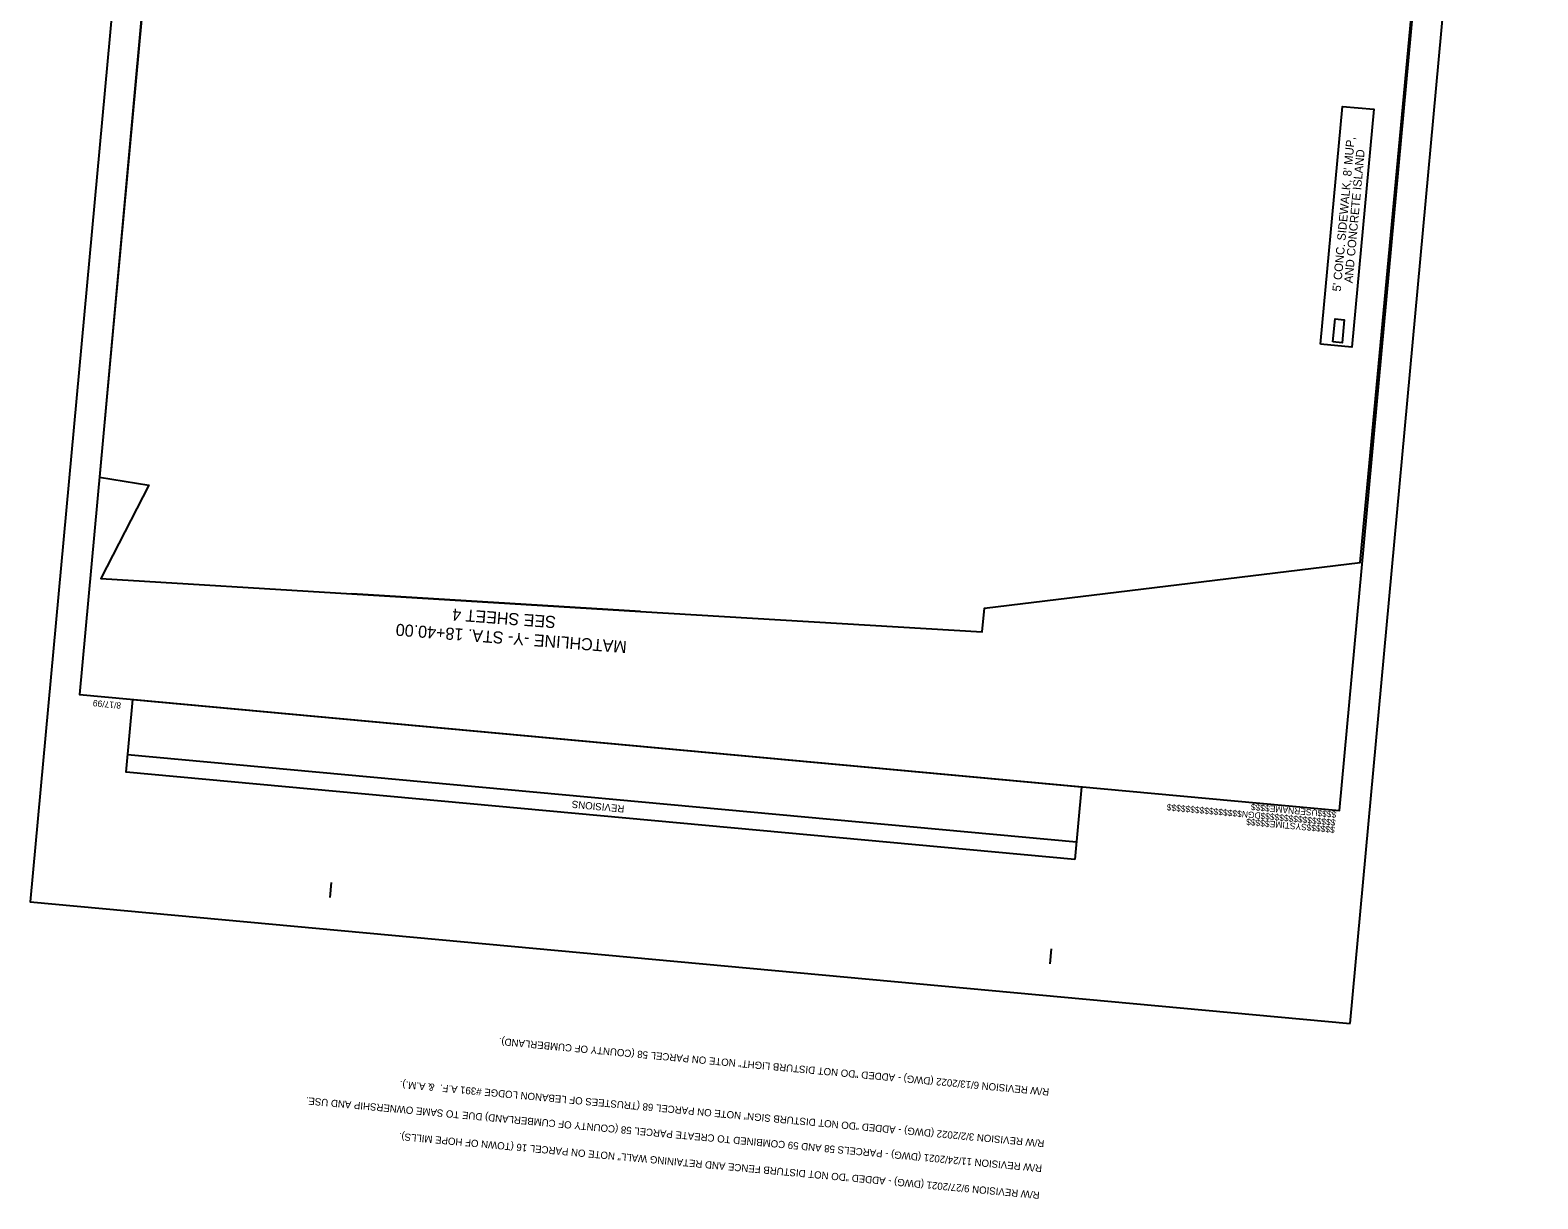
# Model space of a CAD drawing. Extents: x 2011671 to 2012922, y 444781 to 446720.
# Drawn here: x 2011671 to 2012922, y 444781 to 445751 of the extents above; entities that cross this region are included whole.
import ezdxf

# ---------------------------------------------------------------- set-up
doc = ezdxf.new("R2010")
doc.units = 0
for name, color, linetype in [('Matchline', 7, 'Continuous'), ('Matchline Text', 7, 'Continuous'), ('Old_Level_1', 7, 'Continuous'), ('Prop DSN Text', 7, 'Continuous'), ('Prop Shade Medium', 7, 'Continuous'), ('Sheet Block Revision CELL', 7, 'Continuous'), ('Sheet Block System Information CELL', 7, 'Continuous'), ('Sheet Clip Boundary CELL', 7, 'Continuous'), ('Sheet Plan And Profile CELL', 7, 'Continuous'), ('Sheet Plot Border Outside CELL', 7, 'Continuous')]:
    doc.layers.add(name, color=color, linetype=linetype)

msp = doc.modelspace()

# ---------------------------------------------------------------- linework, layer by layer
at = {"layer": 'Matchline'}
msp.add_line((2012177, 445268.5), (2011937.4, 445282.9), dxfattribs=at)
at = {"layer": 'Old_Level_1'}
msp.add_lwpolyline([(2012741.3, 445490.1), (2012759.5, 445687.4), (2012785.4, 445685.1), (2012767.3, 445487.7)], close=True, dxfattribs=at)
at = {"layer": 'Prop Shade Medium'}
msp.add_lwpolyline([(2012751.5, 445492.1), (2012753.3, 445511.1), (2012760.9, 445510.4), (2012759.1, 445491.4)], close=True, dxfattribs=at)
at = {"layer": 'Sheet Block Revision CELL'}
msp.add_line((2012538.7, 445077.1), (2011751.4, 445149.5), dxfattribs=at)
msp.add_lwpolyline([(2012537.4, 445062.6), (2011750.1, 445135), (2011755.6, 445195.3), (2012542.9, 445122.9)], close=True, dxfattribs=at)
at = {"layer": 'Sheet Block System Information CELL'}
msp.add_line((2012757, 445103.2), (2012757, 445103.2), dxfattribs=at)
at = {"layer": 'Sheet Clip Boundary CELL'}
msp.add_lwpolyline([(2011937.4, 445282.9), (2012177, 445268.5), (2012460.6, 445251.6), (2012462.4, 445271.2), (2012774, 445309.1), (2012872.6, 446360.1), (2012827.8, 446363.7), (2012831.1, 446402.1), (2012750.7, 446410.1), (2012511.4, 446429.2), (2011895.9, 446477), (2011878.6, 446288.5), (2011811.3, 446294.7), (2011728, 445379.8), (2011768.9, 445373.1), (2011729.3, 445295.7)], close=True, dxfattribs=at)
at = {"layer": 'Sheet Plan And Profile CELL'}
for p, q in [((2012757, 445103.2), (2012757, 445103.2)), ((2012757, 445103.2), (2012757, 445103.2)), ((2012757, 445103.2), (2012757, 445103.2)), ((2012757, 445103.2), (2012757, 445103.2)), ((2012757, 445103.2), (2012757, 445103.2)), ((2011919.4, 445031.1), (2011920.6, 445043.6)), ((2012516.9, 444976.2), (2012518, 444988.6))]:
    msp.add_line(p, q, dxfattribs=at)
msp.add_lwpolyline([(2011848.8, 446693.1), (2011711.5, 445199.4), (2012757, 445103.2), (2012894.4, 446596.9)], close=True, dxfattribs=at)
at = {"layer": 'Sheet Plot Border Outside CELL'}
msp.add_lwpolyline([(2012765.9, 444926.7), (2012921.6, 446619.5), (2011826.2, 446720.2), (2011670.5, 445027.4)], close=True, dxfattribs=at)

# ---------------------------------------------------------------- texts
at = {"layer": 'Matchline Text'}
for s, p in [('SEE SHEET 4', (2012107.1, 445264.4)), ('MATCHLINE -Y- STA. 18+40.00', (2012165.9, 445243.7))]:
    msp.add_text(s, height=10, rotation=175.6366, dxfattribs=at).set_placement(p)
at = {"layer": 'Old_Level_1'}
for s, p in [('R/W REVISION 6/13/2022 (DWG) - ADDED "DO NOT DISTURB LIGHT" NOTE ON PARCEL 58 (COUNTY OF CUMBERLAND).', (2012516.3, 444872.7)), ('R/W REVISION 3/2/2022 (DWG) - ADDED "DO NOT DISTURB SIGN" NOTE ON PARCEL 68 (TRUSTEES OF LEBANON LODGE #391 A.F.  & A.M.).', (2012512.3, 444829.9)), ('R/W REVISION 11/24/2021 (DWG) - PARCELS 58 AND 59 COMBINED TO CREATE PARCEL 58 (COUNTY OF CUMBERLAND) DUE TO SAME OWNERSHIP AND USE.', (2012510.4, 444809.3)), ('R/W REVISION 9/27/2021 (DWG) - ADDED "DO NOT DISTURB FENCE AND RETAINING WALL" NOTE ON PARCEL 16 (TOWN OF HOPE MILLS).', (2012508.4, 444787))]:
    msp.add_text(s, height=6, rotation=174.7467, dxfattribs=at).set_placement(p)
at = {"layer": 'Prop DSN Text'}
for s, p in [("5' CONC. SIDEWALK, 8' MUP,", (2012758, 445533.6)), ('AND CONCRETE ISLAND', (2012767.8, 445540.6))]:
    msp.add_text(s, height=7, rotation=84.7467, dxfattribs=at).set_placement(p)
at = {"layer": 'Sheet Block Revision CELL'}
msp.add_text('REVISIONS', height=6, rotation=174.7467, dxfattribs=at).set_placement((2012163.8, 445107.5))
at = {"layer": 'Sheet Block System Information CELL'}
for s, p in [('$$$$$$$$$$$$$$$$DGN$$$$$$$$$$$$$$$$', (2012754, 445095.8)), ('$$$$USERNAME$$$$', (2012754.6, 445102.4)), ('$$$$$$SYSTIME$$$$$', (2012753.4, 445089.8))]:
    msp.add_text(s, height=5.25, rotation=174.7467, dxfattribs=at).set_placement(p)
at = {"layer": 'Sheet Plan And Profile CELL'}
msp.add_text('8/17/99', height=5.25, rotation=174.7467, dxfattribs=at).set_placement((2011746.2, 445192.9))

doc.saveas('drawing.dxf')
